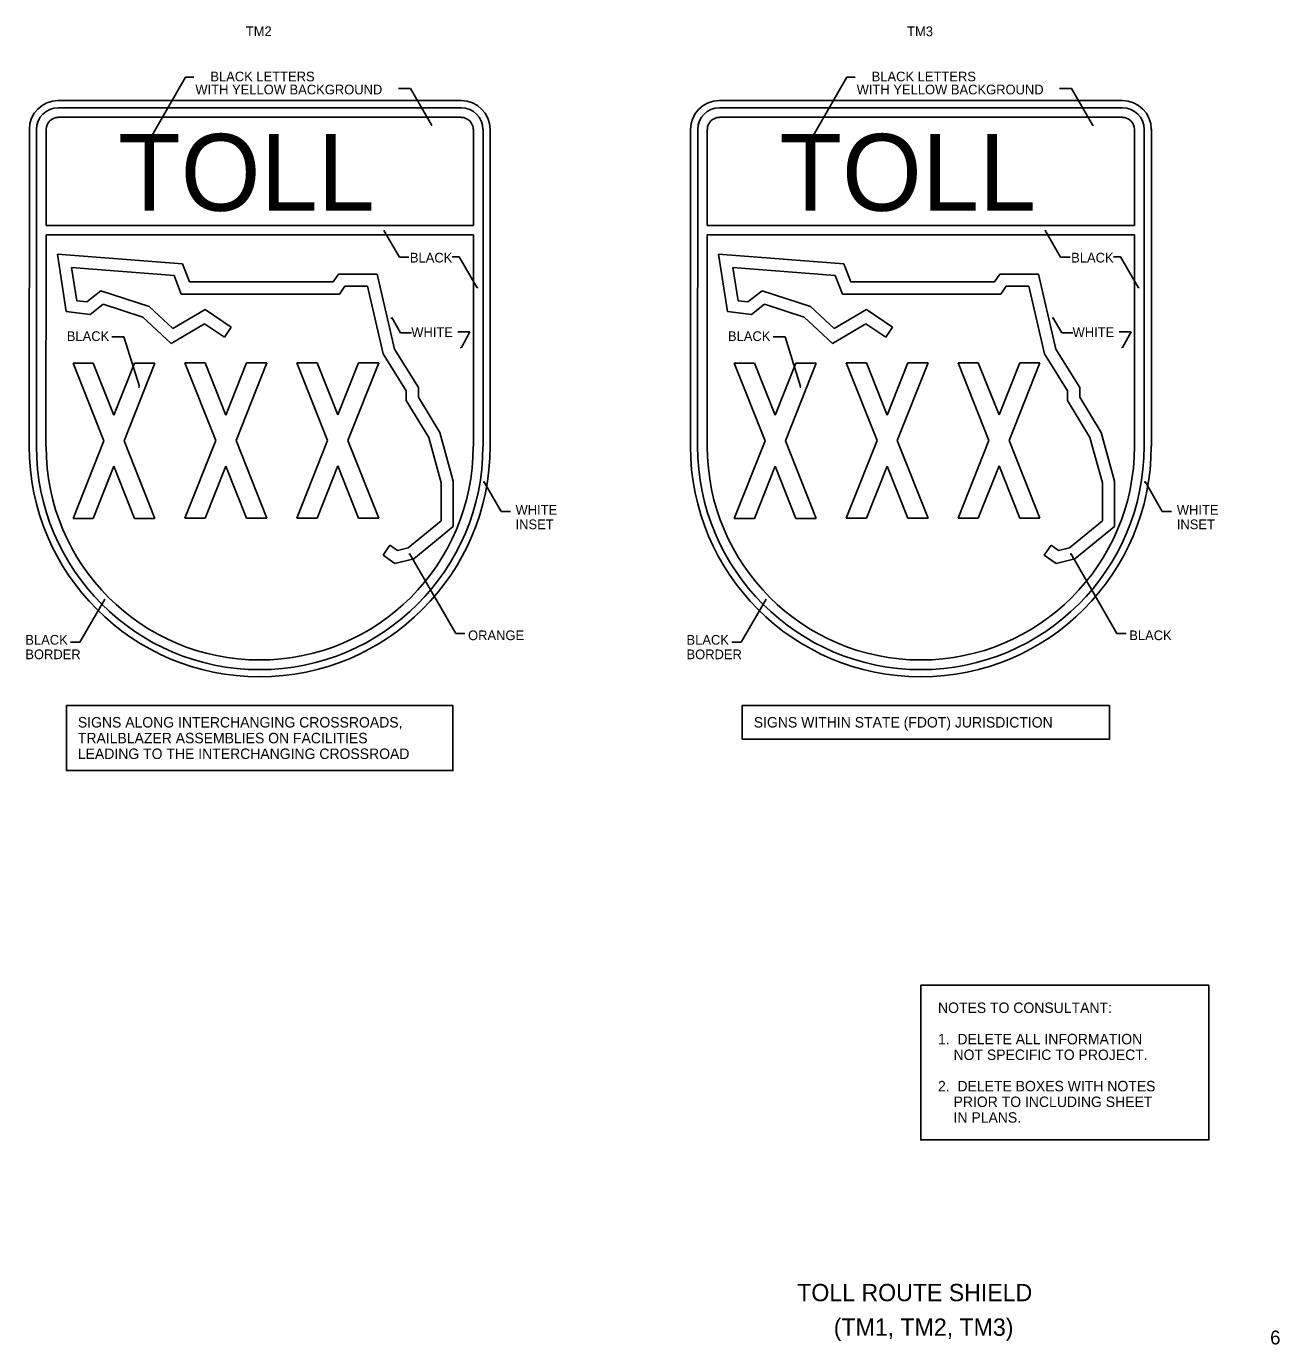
# Model space of a CAD drawing. Extents: x 52204 to 54080, y 10312 to 11487.
# Drawn here: x 52992 to 54080, y 10343 to 11487 of the extents above; entities that cross this region are included whole.
import ezdxf

# ---------------------------------------------------------------- set-up
doc = ezdxf.new("R2010")
doc.units = 0
for name, color, linetype in [('Default', 7, 'Continuous'), ('GSDims', 7, 'Continuous'), ('SignPanel', 7, 'Continuous'), ('TextAlert', 7, 'Continuous'), ('TextMisc', 7, 'Continuous'), ('TextShtNo', 7, 'Continuous')]:
    doc.layers.add(name, color=color, linetype=linetype)

msp = doc.modelspace()

# ---------------------------------------------------------------- linework, layer by layer
at = {"layer": 'GSDims'}
for p, q in [((53096.2, 11384.3), (53129.9, 11442.5)), ((53137.1, 11442.5), (53129.9, 11442.5)), ((53670.2, 11384.3), (53703.8, 11442.5)), ((53711, 11442.5), (53703.8, 11442.5)), ((53314.7, 11432.9), (53325.1, 11432.9)), ((53343.4, 11401.2), (53325.1, 11432.9)), ((53888.4, 11432.9), (53898.9, 11432.9)), ((53917.2, 11401.2), (53898.9, 11432.9)), ((53315.5, 11286.4), (53302.1, 11309.6)), ((53889.4, 11286.4), (53876, 11309.6)), ((53315.5, 11286.4), (53323.6, 11286.4)), ((53361.3, 11286.7), (53367.5, 11286.7)), ((53383, 11259.9), (53367.5, 11286.7)), ((53889.4, 11286.4), (53897.6, 11286.4)), ((53935.2, 11286.7), (53941.5, 11286.7)), ((53957, 11259.9), (53941.5, 11286.7)), ((53316.4, 11220.9), (53308.8, 11234.1)), ((53890.4, 11220.9), (53882.8, 11234.1)), ((53366.2, 11221.7), (53376.7, 11221.7)), ((53369.3, 11208), (53376.7, 11221.7)), ((53940.2, 11221.7), (53950.6, 11221.7)), ((53943.2, 11208), (53950.6, 11221.7)), ((53066, 11217.3), (53076.4, 11217.3)), ((53089.8, 11174.1), (53076.4, 11217.3)), ((53316.4, 11220.9), (53326, 11220.9)), ((53639.9, 11217.3), (53650.4, 11217.3)), ((53663.7, 11174.1), (53650.4, 11217.3)), ((53890.4, 11220.9), (53899.9, 11220.9)), ((53403.7, 11065.8), (53388.8, 11091.7)), ((53977.7, 11065.8), (53962.7, 11091.7)), ((53411.8, 11065.8), (53403.7, 11065.8)), ((53985.7, 11065.8), (53977.7, 11065.8)), ((53364.4, 10959.8), (53324.3, 11029.3)), ((53938.3, 10959.8), (53898.2, 11029.3)), ((53038.2, 10952.3), (53059.7, 10989.6)), ((53612.2, 10952.3), (53633.7, 10989.6)), ((53372.4, 10959.8), (53364.4, 10959.8)), ((53946.4, 10959.8), (53938.3, 10959.8)), ((53038.2, 10952.3), (53030.1, 10952.3)), ((53612.2, 10952.3), (53604.1, 10952.3))]:
    msp.add_line(p, q, dxfattribs=at)
at = {"layer": 'SignPanel'}
for p, q in [((53019.3, 11422.4), (53369.2, 11422.4)), ((53019.3, 11416.1), (53369.2, 11416.1)), ((53593.2, 11422.4), (53943.1, 11422.4)), ((53593.2, 11416.1), (53943.1, 11416.1)), ((53019.3, 11407.8), (53369.2, 11407.8)), ((53593.2, 11407.8), (53943.1, 11407.8)), ((52994.2, 11122.3), (52994.3, 11397.4)), ((53000.4, 11122.3), (53000.5, 11397.4)), ((53008.8, 11314), (53008.8, 11397.4)), ((53379.8, 11314), (53379.8, 11397.4)), ((53388.1, 11122.3), (53388.1, 11397.4)), ((53394.3, 11122.3), (53394.3, 11397.4)), ((53568.1, 11122.3), (53568.2, 11397.4)), ((53574.3, 11122.3), (53574.4, 11397.4)), ((53582.7, 11314), (53582.7, 11397.4)), ((53953.7, 11314), (53953.7, 11397.4)), ((53962, 11122.3), (53962, 11397.4)), ((53968.2, 11122.3), (53968.2, 11397.4)), ((53008.8, 11314), (53061, 11314)), ((53061, 11314), (53379.8, 11314)), ((53582.7, 11314), (53634.9, 11314)), ((53634.9, 11314), (53953.7, 11314)), ((53008.7, 11122.3), (53008.8, 11305.7)), ((53008.8, 11305.7), (53379.8, 11305.7)), ((53379.8, 11122.3), (53379.8, 11305.7)), ((53582.6, 11122.3), (53582.7, 11305.7)), ((53582.7, 11305.7), (53953.7, 11305.7)), ((53953.7, 11122.3), (53953.7, 11305.7)), ((53018.6, 11288.9), (53127.2, 11280.5)), ((53026.3, 11239.2), (53018.6, 11288.9)), ((53127.2, 11280.5), (53133.3, 11264.9)), ((53592.5, 11288.9), (53701.2, 11280.5)), ((53600.3, 11239.2), (53592.5, 11288.9)), ((53701.2, 11280.5), (53707.3, 11264.9)), ((53119.9, 11270.6), (53031, 11277.4)), ((53031, 11277.4), (53035.5, 11248.6)), ((53126.2, 11254.4), (53119.9, 11270.6)), ((53257.9, 11264.9), (53262.6, 11271.8)), ((53262.6, 11271.8), (53296.2, 11271.8)), ((53296.2, 11271.8), (53311.3, 11206.5)), ((53693.8, 11270.6), (53604.9, 11277.4)), ((53604.9, 11277.4), (53609.4, 11248.6)), ((53700.1, 11254.4), (53693.8, 11270.6)), ((53831.9, 11264.9), (53836.6, 11271.8)), ((53836.6, 11271.8), (53870.1, 11271.8)), ((53870.1, 11271.8), (53885.3, 11206.5)), ((53044.1, 11247.6), (53056.4, 11257.3)), ((53056.4, 11257.3), (53098.3, 11243.7)), ((53133.3, 11264.9), (53257.9, 11264.9)), ((53268.2, 11261.4), (53263.5, 11254.4)), ((53287.8, 11261.4), (53268.2, 11261.4)), ((53301.5, 11202.5), (53287.8, 11261.4)), ((53618, 11247.6), (53630.4, 11257.3)), ((53630.4, 11257.3), (53672.3, 11243.7)), ((53707.3, 11264.9), (53831.9, 11264.9)), ((53842.2, 11261.4), (53837.5, 11254.4)), ((53861.8, 11261.4), (53842.2, 11261.4)), ((53875.5, 11202.5), (53861.8, 11261.4)), ((53035.5, 11248.6), (53044.1, 11247.6)), ((53058.5, 11245.6), (53047.1, 11236.6)), ((53092.9, 11234.4), (53058.5, 11245.6)), ((53263.5, 11254.4), (53126.2, 11254.4)), ((53609.4, 11248.6), (53618, 11247.6)), ((53632.5, 11245.6), (53621.1, 11236.6)), ((53666.9, 11234.4), (53632.5, 11245.6)), ((53837.5, 11254.4), (53700.1, 11254.4)), ((53047.1, 11236.6), (53026.3, 11239.2)), ((53117.5, 11211.6), (53092.9, 11234.4)), ((53098.3, 11243.7), (53118.9, 11224.6)), ((53118.9, 11224.6), (53146.8, 11241)), ((53146.8, 11241), (53169.5, 11225.6)), ((53621.1, 11236.6), (53600.3, 11239.2)), ((53691.5, 11211.6), (53666.9, 11234.4)), ((53672.3, 11243.7), (53692.9, 11224.6)), ((53692.9, 11224.6), (53720.8, 11241)), ((53720.8, 11241), (53743.5, 11225.6)), ((53146.4, 11228.6), (53117.5, 11211.6)), ((53163.6, 11217), (53146.4, 11228.6)), ((53169.5, 11225.6), (53163.6, 11217)), ((53720.4, 11228.6), (53691.5, 11211.6)), ((53737.6, 11217), (53720.4, 11228.6)), ((53743.5, 11225.6), (53737.6, 11217)), ((53321.5, 11170.3), (53301.5, 11202.5)), ((53311.3, 11206.5), (53332, 11173.3)), ((53895.5, 11170.3), (53875.5, 11202.5)), ((53885.3, 11206.5), (53906, 11173.3)), ((53049.8, 11194.5), (53032.2, 11194.5)), ((53032.2, 11194.5), (53059, 11127.1)), ((53067.7, 11149.2), (53049.8, 11194.5)), ((53085.7, 11194.5), (53067.7, 11149.2)), ((53076.5, 11127.1), (53103.3, 11194.5)), ((53103.3, 11194.5), (53085.7, 11194.5)), ((53146.9, 11194.6), (53129.3, 11194.6)), ((53129.3, 11194.6), (53156.1, 11127.3)), ((53164.9, 11149.3), (53146.9, 11194.6)), ((53182.9, 11194.6), (53164.9, 11149.3)), ((53173.7, 11127.3), (53200.4, 11194.6)), ((53200.4, 11194.6), (53182.9, 11194.6)), ((53244, 11194.7), (53226.5, 11194.7)), ((53226.5, 11194.7), (53253.2, 11127.4)), ((53262, 11149.5), (53244, 11194.7)), ((53280, 11194.7), (53262, 11149.5)), ((53270.8, 11127.4), (53297.6, 11194.7)), ((53297.6, 11194.7), (53280, 11194.7)), ((53623.7, 11194.5), (53606.2, 11194.5)), ((53606.2, 11194.5), (53632.9, 11127.1)), ((53641.7, 11149.2), (53623.7, 11194.5)), ((53659.7, 11194.5), (53641.7, 11149.2)), ((53650.5, 11127.1), (53677.2, 11194.5)), ((53677.2, 11194.5), (53659.7, 11194.5)), ((53720.8, 11194.6), (53703.3, 11194.6)), ((53703.3, 11194.6), (53730.1, 11127.3)), ((53738.8, 11149.3), (53720.8, 11194.6)), ((53756.8, 11194.6), (53738.8, 11149.3)), ((53747.6, 11127.3), (53774.4, 11194.6)), ((53774.4, 11194.6), (53756.8, 11194.6)), ((53818, 11194.7), (53800.4, 11194.7)), ((53800.4, 11194.7), (53827.2, 11127.4)), ((53836, 11149.5), (53818, 11194.7)), ((53854, 11194.7), (53836, 11149.5)), ((53844.7, 11127.4), (53871.5, 11194.7)), ((53871.5, 11194.7), (53854, 11194.7)), ((53321.5, 11162), (53321.5, 11170.3)), ((53332, 11173.3), (53332, 11164.9)), ((53332, 11164.9), (53350.7, 11134.2)), ((53895.5, 11162), (53895.5, 11170.3)), ((53906, 11173.3), (53906, 11164.9)), ((53906, 11164.9), (53924.7, 11134.2)), ((53341, 11130), (53321.5, 11162)), ((53914.9, 11130), (53895.5, 11162)), ((53350.7, 11134.2), (53362.2, 11092)), ((53924.7, 11134.2), (53936.2, 11092)), ((53059, 11127.1), (53032.2, 11059.8)), ((53103.3, 11059.8), (53076.5, 11127.1)), ((53156.1, 11127.3), (53129.3, 11059.9)), ((53200.4, 11059.9), (53173.7, 11127.3)), ((53253.2, 11127.4), (53226.5, 11060)), ((53297.6, 11060), (53270.8, 11127.4)), ((53351.7, 11090.6), (53341, 11130)), ((53632.9, 11127.1), (53606.2, 11059.8)), ((53677.2, 11059.8), (53650.5, 11127.1)), ((53730.1, 11127.3), (53703.3, 11059.9)), ((53774.4, 11059.9), (53747.6, 11127.3)), ((53827.2, 11127.4), (53800.4, 11060)), ((53871.5, 11060), (53844.7, 11127.4)), ((53925.7, 11090.6), (53914.9, 11130)), ((53049.8, 11059.8), (53067.7, 11105.1)), ((53067.7, 11105.1), (53085.7, 11059.8)), ((53146.9, 11059.9), (53164.9, 11105.2)), ((53164.9, 11105.2), (53182.9, 11059.9)), ((53244, 11060), (53262, 11105.3)), ((53262, 11105.3), (53280, 11060)), ((53623.7, 11059.8), (53641.7, 11105.1)), ((53641.7, 11105.1), (53659.7, 11059.8)), ((53720.8, 11059.9), (53738.8, 11105.2)), ((53738.8, 11105.2), (53756.8, 11059.9)), ((53818, 11060), (53836, 11105.3)), ((53836, 11105.3), (53854, 11060)), ((53351.7, 11057.7), (53351.7, 11090.6)), ((53362.2, 11092), (53362.2, 11052.7)), ((53925.7, 11057.7), (53925.7, 11090.6)), ((53936.2, 11092), (53936.2, 11052.7)), ((53032.2, 11059.8), (53049.8, 11059.8)), ((53085.7, 11059.8), (53103.3, 11059.8)), ((53129.3, 11059.9), (53146.9, 11059.9)), ((53182.9, 11059.9), (53200.4, 11059.9)), ((53226.5, 11060), (53244, 11060)), ((53280, 11060), (53297.6, 11060)), ((53323.1, 11034.2), (53351.7, 11057.7)), ((53362.2, 11052.7), (53327.9, 11024.6)), ((53606.2, 11059.8), (53623.7, 11059.8)), ((53659.7, 11059.8), (53677.2, 11059.8)), ((53703.3, 11059.9), (53720.8, 11059.9)), ((53756.8, 11059.9), (53774.4, 11059.9)), ((53800.4, 11060), (53818, 11060)), ((53854, 11060), (53871.5, 11060)), ((53897.1, 11034.2), (53925.7, 11057.7)), ((53936.2, 11052.7), (53901.9, 11024.6)), ((53301.3, 11027.8), (53307.2, 11036.4)), ((53311.6, 11020.7), (53301.3, 11027.8)), ((53307.2, 11036.4), (53313.7, 11031.9)), ((53313.7, 11031.9), (53323.1, 11034.2)), ((53875.2, 11027.8), (53881.2, 11036.4)), ((53885.5, 11020.7), (53875.2, 11027.8)), ((53881.2, 11036.4), (53887.7, 11031.9)), ((53887.7, 11031.9), (53897.1, 11034.2)), ((53327.9, 11024.6), (53311.6, 11020.7)), ((53901.9, 11024.6), (53885.5, 11020.7))]:
    msp.add_line(p, q, dxfattribs=at)
for centre, radius, start, end in [((53019.3, 11397.3), 25, 90, 179.9792), ((53019.3, 11397.3), 18.8, 90, 179.9792), ((53369.2, 11397.3), 25, 0, 90), ((53369.2, 11397.3), 18.8, 0, 90), ((53593.2, 11397.3), 25, 90, 179.9792), ((53593.2, 11397.3), 18.8, 90, 179.9792), ((53943.1, 11397.3), 25, 0, 90), ((53943.1, 11397.3), 18.8, 0, 90), ((53019.3, 11397.3), 10.4, 90, 179.9792), ((53369.2, 11397.3), 10.4, 0, 90), ((53593.2, 11397.3), 10.4, 90, 179.9792), ((53943.1, 11397.3), 10.4, 0, 90), ((53194.2, 11122.3), 200, 180, 0), ((53194.2, 11122.3), 193.8, 180, 0), ((53194.2, 11122.3), 185.4, 180, 0), ((53768.1, 11122.3), 200, 180, 0), ((53768.1, 11122.3), 193.8, 180, 0), ((53768.1, 11122.3), 185.4, 180, 0)]:
    msp.add_arc(centre, radius, start, end, dxfattribs=at)
at = {"layer": 'TextAlert'}
for points in [[(53026.4, 10897.3), (53361.9, 10897.3), (53361.9, 10841), (53026.4, 10841)], [(53613.1, 10897.3), (53932, 10897.3), (53932, 10868.3), (53613.1, 10868.3)], [(53768, 10654.7), (54018.2, 10654.7), (54018.2, 10520.4), (53768, 10520.4)]]:
    msp.add_lwpolyline(points, close=True, dxfattribs=at)

# ---------------------------------------------------------------- texts
at = {"layer": 'Default'}
for s, p in [('TM2', (53182.2, 11478.2)), ('TM3', (53756.2, 11478.2))]:
    msp.add_text(s, height=8.4, dxfattribs=at).set_placement(p)
at = {"layer": 'GSDims'}
for s, p in [('BLACK LETTERS', (53151.4, 11439)), ('BLACK LETTERS', (53725.4, 11439)), ('WITH YELLOW BACKGROUND', (53138.4, 11427.7)), ('WITH YELLOW BACKGROUND', (53712.4, 11427.7)), ('.', (53094.7, 11383.5)), ('.', (53668.7, 11383.5)), ('BLACK', (53324.6, 11281.8)), ('BLACK', (53898.6, 11281.8)), ('.', (53307, 11232.9)), ('.', (53881, 11232.9)), ('BLACK', (53026.8, 11213.7)), ('WHITE', (53325.8, 11217.1)), ('BLACK', (53600.7, 11213.7)), ('WHITE', (53899.8, 11217.1)), ('.', (53088, 11173)), ('.', (53661.9, 11173)), ('.', (53387, 11090.5)), ('.', (53960.9, 11090.5)), ('WHITE', (53416.3, 11063)), ('WHITE', (53990.3, 11063)), ('INSET', (53416.3, 11050.4)), ('INSET', (53990.3, 11050.4)), ('.', (53322.5, 11028.1)), ('.', (53896.5, 11028.1)), ('.', (53057.9, 10988.3)), ('.', (53631.9, 10988.3)), ('BLACK', (52990.8, 10950.2)), ('ORANGE', (53375.1, 10954.1)), ('BLACK', (53564.7, 10950.2)), ('BLACK', (53949, 10954.1)), ('BORDER', (52990.8, 10937.6)), ('BORDER', (53564.7, 10937.6))]:
    msp.add_text(s, height=8.4, dxfattribs=at).set_placement(p)
for rotation, p in [(90, (53344.2, 11399.3)), (90, (53918, 11399.3)), (90, (53303.1, 11308)), (90, (53877, 11308)), (301.5608, (53367.4, 11208.9)), (301.5608, (53941.4, 11208.9))]:
    msp.add_text('.', height=8.4, rotation=rotation, dxfattribs=at).set_placement(p)
at = {"layer": 'SignPanel'}
for p in [(53071.2, 11326.7), (53645.2, 11326.7)]:
    msp.add_text('TOLL', height=66.65, dxfattribs=at).set_placement(p)
for p in [(53384, 11258.4), (53957.9, 11258.4)]:
    msp.add_text('.', height=7.2, rotation=90, dxfattribs=at).set_placement(p)
at = {"layer": 'TextAlert'}
for s, p in [('SIGNS ALONG INTERCHANGING CROSSROADS,', (53036.4, 10878.3)), ('SIGNS WITHIN STATE (FDOT) JURISDICTION', (53623.1, 10878.3)), ('TRAILBLAZER ASSEMBLIES ON FACILITIES', (53036.4, 10864.6)), ('LEADING TO THE INTERCHANGING CROSSROAD', (53036.4, 10851)), ('NOTES TO CONSULTANT:', (53783, 10630.6)), ('1.  DELETE ALL INFORMATION', (53783, 10603.4)), ('    NOT SPECIFIC TO PROJECT.', (53783, 10589.8)), ('2.  DELETE BOXES WITH NOTES', (53783, 10562.6)), ('    PRIOR TO INCLUDING SHEET', (53783, 10549)), ('    IN PLANS.', (53783, 10535.4))]:
    msp.add_text(s, height=9.072, dxfattribs=at).set_placement(p)
at = {"layer": 'TextMisc'}
for s, p in [('   TOLL ROUTE SHIELD    ', (53644.1, 10380.5)), ('    (TM1, TM2, TM3)     ', (53670.2, 10350.5))]:
    msp.add_text(s, height=15, rotation=360, dxfattribs=at).set_placement(p)
at = {"layer": 'TextShtNo'}
msp.add_text('6', height=12, rotation=360, dxfattribs=at).set_placement((54071.3, 10343))

doc.saveas('drawing.dxf')
